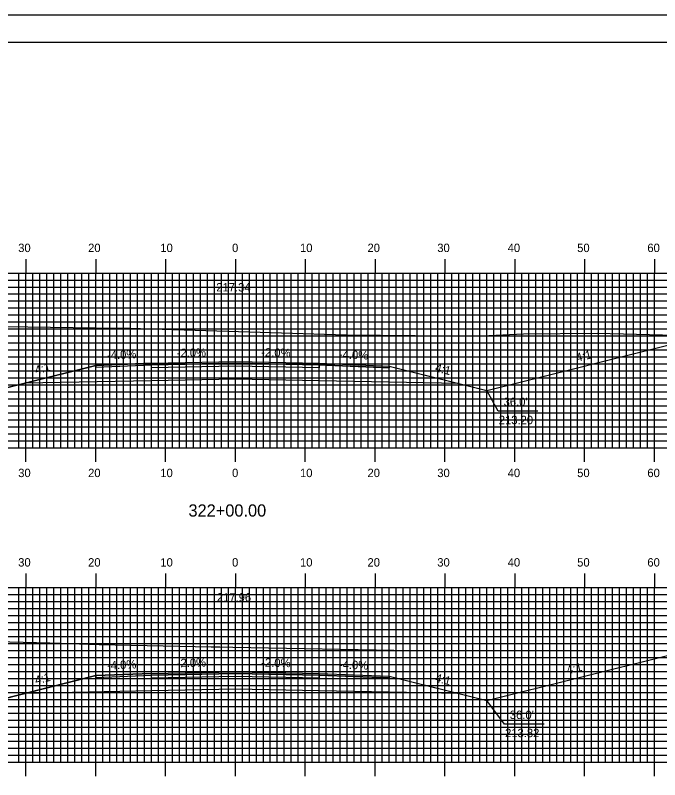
# Model space of a CAD drawing. Extents: x 1820424 to 1820768, y 442591 to 442811.
# Drawn here: x 1820558.7 to 1820650.9, y 442701.2 to 442810.5 of the extents above; entities that cross this region are included whole.
import ezdxf

# ---------------------------------------------------------------- set-up
doc = ezdxf.new("R2010")
doc.units = 0
for name, color, linetype in [('ANNOTATION', 7, 'Continuous'), ('BORDER', 7, 'Continuous'), ('D_Roadway_Centerline', 7, 'Continuous'), ('D_Roadway_Centerline_Text', 7, 'Continuous'), ('D_Roadway_Edge_Shoulder', 7, 'Continuous'), ('D_Roadway_Edge_TW', 7, 'Continuous'), ('D_Roadway_Pavement', 7, 'Continuous'), ('D_Roadway_SlopeLines', 7, 'Continuous'), ('D_Roadway_SubGrade', 7, 'Continuous'), ('H_V ANNOTATION', 7, 'Continuous'), ('MAJOR', 7, 'Continuous'), ('MINOR', 7, 'Continuous'), ('PLOT BOUNDARY', 7, 'Continuous'), ('S_Roadway_Centerline', 7, 'Continuous')]:
    doc.layers.add(name, color=color, linetype=linetype)

msp = doc.modelspace()

# ---------------------------------------------------------------- linework, layer by layer
at = {"layer": 'ANNOTATION'}
for points in [[(1820633.52, 442753.92), (1820627.82, 442753.92), (1820626.2, 442756.86)], [(1820634.41, 442709.14), (1820628.72, 442709.14), (1820626.2, 442712.49)]]:
    msp.add_lwpolyline(points, dxfattribs=at)
at = {"layer": 'BORDER'}
msp.add_lwpolyline([(1820440.6, 442596.67), (1820760.6, 442596.67), (1820760.6, 442806.67), (1820440.6, 442806.67)], close=True, dxfattribs=at)
at = {"layer": 'D_Roadway_Centerline'}
for points in [[(1820513.87, 442766.87), (1820515.12, 442766.81), (1820516.37, 442766.67), (1820517.62, 442766.46), (1820518.87, 442766.19), (1820556.03, 442756.9), (1820560.03, 442757.9), (1820570.2, 442760.44), (1820578.2, 442760.76), (1820590.2, 442761), (1820602.2, 442760.76), (1820612.2, 442760.36), (1820622.2, 442757.86), (1820626.2, 442756.86), (1820654.98, 442764.06), (1820656.23, 442764.33), (1820657.48, 442764.52), (1820658.73, 442764.63), (1820659.98, 442764.66)], [(1820513.66, 442722.46), (1820514.91, 442722.44), (1820516.16, 442722.33), (1820517.41, 442722.14), (1820518.66, 442721.87), (1820556.03, 442712.52), (1820560.03, 442713.52), (1820570.2, 442716.07), (1820578.2, 442716.39), (1820590.2, 442716.63), (1820602.2, 442716.39), (1820612.2, 442715.99), (1820622.2, 442713.49), (1820626.2, 442712.49), (1820652.27, 442719), (1820653.52, 442719.27), (1820654.77, 442719.47), (1820656.02, 442719.58), (1820657.27, 442719.62)]]:
    msp.add_lwpolyline(points, dxfattribs=at)
at = {"layer": 'D_Roadway_Edge_Shoulder'}
for points in [[(1820578.2, 442760.76), (1820570.2, 442760.44), (1820570.2, 442760.19), (1820578.2, 442760.51)], [(1820602.2, 442760.76), (1820612.2, 442760.36), (1820612.2, 442760.11), (1820602.2, 442760.51)], [(1820578.2, 442716.39), (1820570.2, 442716.07), (1820570.2, 442715.82), (1820578.2, 442716.14)], [(1820602.2, 442716.39), (1820612.2, 442715.99), (1820612.2, 442715.74), (1820602.2, 442716.14)]]:
    msp.add_lwpolyline(points, close=True, dxfattribs=at)
at = {"layer": 'D_Roadway_Edge_TW'}
for points in [[(1820578.2, 442760.51), (1820578.2, 442760.76), (1820590.2, 442761), (1820602.2, 442760.76), (1820602.2, 442760.51), (1820590.2, 442760.75)], [(1820578.2, 442716.14), (1820578.2, 442716.39), (1820590.2, 442716.63), (1820602.2, 442716.39), (1820602.2, 442716.14), (1820590.2, 442716.38)]]:
    msp.add_lwpolyline(points, close=True, dxfattribs=at)
at = {"layer": 'D_Roadway_Pavement'}
for points in [[(1820578.2, 442760.09), (1820578.2, 442760.51), (1820590.2, 442760.75), (1820602.2, 442760.51), (1820602.2, 442760.09), (1820590.2, 442760.33)], [(1820578.2, 442715.72), (1820578.2, 442716.14), (1820590.2, 442716.38), (1820602.2, 442716.14), (1820602.2, 442715.72), (1820590.2, 442715.96)]]:
    msp.add_lwpolyline(points, close=True, dxfattribs=at)
at = {"layer": 'D_Roadway_SlopeLines'}
for points in [[(1820626.2, 442756.86), (1820654.98, 442764.06), (1820656.23, 442764.33), (1820657.48, 442764.52), (1820658.73, 442764.63), (1820659.98, 442764.66)], [(1820570.2, 442760.44), (1820556.03, 442756.9)], [(1820612.2, 442760.36), (1820626.2, 442756.86)], [(1820626.2, 442712.49), (1820652.27, 442719), (1820653.52, 442719.27), (1820654.77, 442719.47), (1820656.02, 442719.58), (1820657.27, 442719.62)], [(1820570.2, 442716.07), (1820556.03, 442712.52)], [(1820612.2, 442715.99), (1820626.2, 442712.49)]]:
    msp.add_lwpolyline(points, dxfattribs=at)
at = {"layer": 'D_Roadway_SubGrade'}
for points in [[(1820578.2, 442758.26), (1820560.03, 442757.9), (1820570.2, 442760.44), (1820570.2, 442760.19), (1820578.2, 442760.51), (1820590.2, 442760.75), (1820602.2, 442760.51), (1820612.2, 442760.11), (1820612.2, 442760.36), (1820622.2, 442757.86), (1820602.2, 442758.26), (1820590.2, 442758.5)], [(1820578.2, 442713.89), (1820560.03, 442713.52), (1820570.2, 442716.07), (1820570.2, 442715.82), (1820578.2, 442716.14), (1820590.2, 442716.38), (1820602.2, 442716.14), (1820612.2, 442715.74), (1820612.2, 442715.99), (1820622.2, 442713.49), (1820602.2, 442713.89), (1820590.2, 442714.13)]]:
    msp.add_lwpolyline(points, close=True, dxfattribs=at)
at = {"layer": 'MAJOR'}
for p, q in [((1820560.2, 442775.67), (1820560.2, 442773.67)), ((1820570.2, 442775.67), (1820570.2, 442773.67)), ((1820580.2, 442775.67), (1820580.2, 442773.67)), ((1820590.2, 442775.67), (1820590.2, 442773.67)), ((1820600.2, 442775.67), (1820600.2, 442773.67)), ((1820610.2, 442775.67), (1820610.2, 442773.67)), ((1820620.2, 442775.67), (1820620.2, 442773.67)), ((1820630.2, 442775.67), (1820630.2, 442773.67)), ((1820640.2, 442775.67), (1820640.2, 442773.67)), ((1820650.2, 442775.67), (1820650.2, 442773.67)), ((1820450.2, 442773.67), (1820730.2, 442773.67)), ((1820450.2, 442773.67), (1820730.2, 442773.67)), ((1820560.2, 442748.67), (1820560.2, 442773.67)), ((1820570.2, 442748.67), (1820570.2, 442773.67)), ((1820580.2, 442748.67), (1820580.2, 442773.67)), ((1820590.2, 442748.67), (1820590.2, 442773.67)), ((1820600.2, 442748.67), (1820600.2, 442773.67)), ((1820610.2, 442748.67), (1820610.2, 442773.67)), ((1820620.2, 442748.67), (1820620.2, 442773.67)), ((1820630.2, 442748.67), (1820630.2, 442773.67)), ((1820640.2, 442748.67), (1820640.2, 442773.67)), ((1820650.2, 442748.67), (1820650.2, 442773.67)), ((1820450.2, 442768.67), (1820730.2, 442768.67)), ((1820450.2, 442763.67), (1820730.2, 442763.67)), ((1820450.2, 442758.67), (1820730.2, 442758.67)), ((1820450.2, 442753.67), (1820730.2, 442753.67)), ((1820450.2, 442748.67), (1820730.2, 442748.67)), ((1820450.2, 442748.67), (1820730.2, 442748.67)), ((1820560.2, 442746.66), (1820560.2, 442748.67)), ((1820570.2, 442746.66), (1820570.2, 442748.67)), ((1820580.2, 442746.66), (1820580.2, 442748.67)), ((1820590.2, 442746.66), (1820590.2, 442748.67)), ((1820600.2, 442746.66), (1820600.2, 442748.67)), ((1820610.2, 442746.66), (1820610.2, 442748.67)), ((1820620.2, 442746.66), (1820620.2, 442748.67)), ((1820630.2, 442746.66), (1820630.2, 442748.67)), ((1820640.2, 442746.66), (1820640.2, 442748.67)), ((1820650.2, 442746.66), (1820650.2, 442748.67)), ((1820560.2, 442730.67), (1820560.2, 442728.67)), ((1820570.2, 442730.67), (1820570.2, 442728.67)), ((1820580.2, 442730.67), (1820580.2, 442728.67)), ((1820590.2, 442730.67), (1820590.2, 442728.67)), ((1820600.2, 442730.67), (1820600.2, 442728.67)), ((1820610.2, 442730.67), (1820610.2, 442728.67)), ((1820620.2, 442730.67), (1820620.2, 442728.67)), ((1820630.2, 442730.67), (1820630.2, 442728.67)), ((1820640.2, 442730.67), (1820640.2, 442728.67)), ((1820650.2, 442730.67), (1820650.2, 442728.67)), ((1820450.2, 442728.67), (1820730.2, 442728.67)), ((1820450.2, 442728.67), (1820730.2, 442728.67)), ((1820560.2, 442703.67), (1820560.2, 442728.67)), ((1820570.2, 442703.67), (1820570.2, 442728.67)), ((1820580.2, 442703.67), (1820580.2, 442728.67)), ((1820590.2, 442703.67), (1820590.2, 442728.67)), ((1820600.2, 442703.67), (1820600.2, 442728.67)), ((1820610.2, 442703.67), (1820610.2, 442728.67)), ((1820620.2, 442703.67), (1820620.2, 442728.67)), ((1820630.2, 442703.67), (1820630.2, 442728.67)), ((1820640.2, 442703.67), (1820640.2, 442728.67)), ((1820650.2, 442703.67), (1820650.2, 442728.67)), ((1820450.2, 442723.67), (1820730.2, 442723.67)), ((1820450.2, 442718.67), (1820730.2, 442718.67)), ((1820450.2, 442713.67), (1820730.2, 442713.67)), ((1820450.2, 442708.67), (1820730.2, 442708.67)), ((1820450.2, 442703.67), (1820730.2, 442703.67)), ((1820450.2, 442703.67), (1820730.2, 442703.67)), ((1820560.2, 442701.66), (1820560.2, 442703.67)), ((1820570.2, 442701.66), (1820570.2, 442703.67)), ((1820580.2, 442701.66), (1820580.2, 442703.67)), ((1820590.2, 442701.66), (1820590.2, 442703.67)), ((1820600.2, 442701.66), (1820600.2, 442703.67)), ((1820610.2, 442701.66), (1820610.2, 442703.67)), ((1820620.2, 442701.66), (1820620.2, 442703.67)), ((1820630.2, 442701.66), (1820630.2, 442703.67)), ((1820640.2, 442701.66), (1820640.2, 442703.67)), ((1820650.2, 442701.66), (1820650.2, 442703.67))]:
    msp.add_line(p, q, dxfattribs=at)
at = {"layer": 'MINOR'}
for p, q in [((1820559.2, 442748.67), (1820559.2, 442773.67)), ((1820561.2, 442748.67), (1820561.2, 442773.67)), ((1820562.2, 442748.67), (1820562.2, 442773.67)), ((1820563.2, 442748.67), (1820563.2, 442773.67)), ((1820564.2, 442748.67), (1820564.2, 442773.67)), ((1820565.2, 442748.67), (1820565.2, 442773.67)), ((1820566.2, 442748.67), (1820566.2, 442773.67)), ((1820567.2, 442748.67), (1820567.2, 442773.67)), ((1820568.2, 442748.67), (1820568.2, 442773.67)), ((1820569.2, 442748.67), (1820569.2, 442773.67)), ((1820571.2, 442748.67), (1820571.2, 442773.67)), ((1820572.2, 442748.67), (1820572.2, 442773.67)), ((1820573.2, 442748.67), (1820573.2, 442773.67)), ((1820574.2, 442748.67), (1820574.2, 442773.67)), ((1820575.2, 442748.67), (1820575.2, 442773.67)), ((1820576.2, 442748.67), (1820576.2, 442773.67)), ((1820577.2, 442748.67), (1820577.2, 442773.67)), ((1820578.2, 442748.67), (1820578.2, 442773.67)), ((1820579.2, 442748.67), (1820579.2, 442773.67)), ((1820581.2, 442748.67), (1820581.2, 442773.67)), ((1820582.2, 442748.67), (1820582.2, 442773.67)), ((1820583.2, 442748.67), (1820583.2, 442773.67)), ((1820584.2, 442748.67), (1820584.2, 442773.67)), ((1820585.2, 442748.67), (1820585.2, 442773.67)), ((1820586.2, 442748.67), (1820586.2, 442773.67)), ((1820587.2, 442748.67), (1820587.2, 442773.67)), ((1820588.2, 442748.67), (1820588.2, 442773.67)), ((1820589.2, 442748.67), (1820589.2, 442773.67)), ((1820591.2, 442748.67), (1820591.2, 442773.67)), ((1820592.2, 442748.67), (1820592.2, 442773.67)), ((1820593.2, 442748.67), (1820593.2, 442773.67)), ((1820594.2, 442748.67), (1820594.2, 442773.67)), ((1820595.2, 442748.67), (1820595.2, 442773.67)), ((1820596.2, 442748.67), (1820596.2, 442773.67)), ((1820597.2, 442748.67), (1820597.2, 442773.67)), ((1820598.2, 442748.67), (1820598.2, 442773.67)), ((1820599.2, 442748.67), (1820599.2, 442773.67)), ((1820601.2, 442748.67), (1820601.2, 442773.67)), ((1820602.2, 442748.67), (1820602.2, 442773.67)), ((1820603.2, 442748.67), (1820603.2, 442773.67)), ((1820604.2, 442748.67), (1820604.2, 442773.67)), ((1820605.2, 442748.67), (1820605.2, 442773.67)), ((1820606.2, 442748.67), (1820606.2, 442773.67)), ((1820607.2, 442748.67), (1820607.2, 442773.67)), ((1820608.2, 442748.67), (1820608.2, 442773.67)), ((1820609.2, 442748.67), (1820609.2, 442773.67)), ((1820611.2, 442748.67), (1820611.2, 442773.67)), ((1820612.2, 442748.67), (1820612.2, 442773.67)), ((1820613.2, 442748.67), (1820613.2, 442773.67)), ((1820614.2, 442748.67), (1820614.2, 442773.67)), ((1820615.2, 442748.67), (1820615.2, 442773.67)), ((1820616.2, 442748.67), (1820616.2, 442773.67)), ((1820617.2, 442748.67), (1820617.2, 442773.67)), ((1820618.2, 442748.67), (1820618.2, 442773.67)), ((1820619.2, 442748.67), (1820619.2, 442773.67)), ((1820621.2, 442748.67), (1820621.2, 442773.67)), ((1820622.2, 442748.67), (1820622.2, 442773.67)), ((1820623.2, 442748.67), (1820623.2, 442773.67)), ((1820624.2, 442748.67), (1820624.2, 442773.67)), ((1820625.2, 442748.67), (1820625.2, 442773.67)), ((1820626.2, 442748.67), (1820626.2, 442773.67)), ((1820627.2, 442748.67), (1820627.2, 442773.67)), ((1820628.2, 442748.67), (1820628.2, 442773.67)), ((1820629.2, 442748.67), (1820629.2, 442773.67)), ((1820631.2, 442748.67), (1820631.2, 442773.67)), ((1820632.2, 442748.67), (1820632.2, 442773.67)), ((1820633.2, 442748.67), (1820633.2, 442773.67)), ((1820634.2, 442748.67), (1820634.2, 442773.67)), ((1820635.2, 442748.67), (1820635.2, 442773.67)), ((1820636.2, 442748.67), (1820636.2, 442773.67)), ((1820637.2, 442748.67), (1820637.2, 442773.67)), ((1820638.2, 442748.67), (1820638.2, 442773.67)), ((1820639.2, 442748.67), (1820639.2, 442773.67)), ((1820641.2, 442748.67), (1820641.2, 442773.67)), ((1820642.2, 442748.67), (1820642.2, 442773.67)), ((1820643.2, 442748.67), (1820643.2, 442773.67)), ((1820644.2, 442748.67), (1820644.2, 442773.67)), ((1820645.2, 442748.67), (1820645.2, 442773.67)), ((1820646.2, 442748.67), (1820646.2, 442773.67)), ((1820647.2, 442748.67), (1820647.2, 442773.67)), ((1820648.2, 442748.67), (1820648.2, 442773.67)), ((1820649.2, 442748.67), (1820649.2, 442773.67)), ((1820450.2, 442772.67), (1820730.2, 442772.67)), ((1820450.2, 442771.67), (1820730.2, 442771.67)), ((1820450.2, 442770.67), (1820730.2, 442770.67)), ((1820450.2, 442769.67), (1820730.2, 442769.67)), ((1820450.2, 442767.67), (1820730.2, 442767.67)), ((1820450.2, 442766.67), (1820730.2, 442766.67)), ((1820450.2, 442765.67), (1820730.2, 442765.67)), ((1820450.2, 442764.67), (1820730.2, 442764.67)), ((1820450.2, 442762.67), (1820730.2, 442762.67)), ((1820450.2, 442761.67), (1820730.2, 442761.67)), ((1820450.2, 442760.67), (1820730.2, 442760.67)), ((1820450.2, 442759.67), (1820730.2, 442759.67)), ((1820450.2, 442757.67), (1820730.2, 442757.67)), ((1820450.2, 442756.67), (1820730.2, 442756.67)), ((1820450.2, 442755.67), (1820730.2, 442755.67)), ((1820450.2, 442754.67), (1820730.2, 442754.67)), ((1820450.2, 442752.67), (1820730.2, 442752.67)), ((1820450.2, 442751.67), (1820730.2, 442751.67)), ((1820450.2, 442750.67), (1820730.2, 442750.67)), ((1820450.2, 442749.67), (1820730.2, 442749.67)), ((1820559.2, 442703.67), (1820559.2, 442728.67)), ((1820561.2, 442703.67), (1820561.2, 442728.67)), ((1820562.2, 442703.67), (1820562.2, 442728.67)), ((1820563.2, 442703.67), (1820563.2, 442728.67)), ((1820564.2, 442703.67), (1820564.2, 442728.67)), ((1820565.2, 442703.67), (1820565.2, 442728.67)), ((1820566.2, 442703.67), (1820566.2, 442728.67)), ((1820567.2, 442703.67), (1820567.2, 442728.67)), ((1820568.2, 442703.67), (1820568.2, 442728.67)), ((1820569.2, 442703.67), (1820569.2, 442728.67)), ((1820571.2, 442703.67), (1820571.2, 442728.67)), ((1820572.2, 442703.67), (1820572.2, 442728.67)), ((1820573.2, 442703.67), (1820573.2, 442728.67)), ((1820574.2, 442703.67), (1820574.2, 442728.67)), ((1820575.2, 442703.67), (1820575.2, 442728.67)), ((1820576.2, 442703.67), (1820576.2, 442728.67)), ((1820577.2, 442703.67), (1820577.2, 442728.67)), ((1820578.2, 442703.67), (1820578.2, 442728.67)), ((1820579.2, 442703.67), (1820579.2, 442728.67)), ((1820581.2, 442703.67), (1820581.2, 442728.67)), ((1820582.2, 442703.67), (1820582.2, 442728.67)), ((1820583.2, 442703.67), (1820583.2, 442728.67)), ((1820584.2, 442703.67), (1820584.2, 442728.67)), ((1820585.2, 442703.67), (1820585.2, 442728.67)), ((1820586.2, 442703.67), (1820586.2, 442728.67)), ((1820587.2, 442703.67), (1820587.2, 442728.67)), ((1820588.2, 442703.67), (1820588.2, 442728.67)), ((1820589.2, 442703.67), (1820589.2, 442728.67)), ((1820591.2, 442703.67), (1820591.2, 442728.67)), ((1820592.2, 442703.67), (1820592.2, 442728.67)), ((1820593.2, 442703.67), (1820593.2, 442728.67)), ((1820594.2, 442703.67), (1820594.2, 442728.67)), ((1820595.2, 442703.67), (1820595.2, 442728.67)), ((1820596.2, 442703.67), (1820596.2, 442728.67)), ((1820597.2, 442703.67), (1820597.2, 442728.67)), ((1820598.2, 442703.67), (1820598.2, 442728.67)), ((1820599.2, 442703.67), (1820599.2, 442728.67)), ((1820601.2, 442703.67), (1820601.2, 442728.67)), ((1820602.2, 442703.67), (1820602.2, 442728.67)), ((1820603.2, 442703.67), (1820603.2, 442728.67)), ((1820604.2, 442703.67), (1820604.2, 442728.67)), ((1820605.2, 442703.67), (1820605.2, 442728.67)), ((1820606.2, 442703.67), (1820606.2, 442728.67)), ((1820607.2, 442703.67), (1820607.2, 442728.67)), ((1820608.2, 442703.67), (1820608.2, 442728.67)), ((1820609.2, 442703.67), (1820609.2, 442728.67)), ((1820611.2, 442703.67), (1820611.2, 442728.67)), ((1820612.2, 442703.67), (1820612.2, 442728.67)), ((1820613.2, 442703.67), (1820613.2, 442728.67)), ((1820614.2, 442703.67), (1820614.2, 442728.67)), ((1820615.2, 442703.67), (1820615.2, 442728.67)), ((1820616.2, 442703.67), (1820616.2, 442728.67)), ((1820617.2, 442703.67), (1820617.2, 442728.67)), ((1820618.2, 442703.67), (1820618.2, 442728.67)), ((1820619.2, 442703.67), (1820619.2, 442728.67)), ((1820621.2, 442703.67), (1820621.2, 442728.67)), ((1820622.2, 442703.67), (1820622.2, 442728.67)), ((1820623.2, 442703.67), (1820623.2, 442728.67)), ((1820624.2, 442703.67), (1820624.2, 442728.67)), ((1820625.2, 442703.67), (1820625.2, 442728.67)), ((1820626.2, 442703.67), (1820626.2, 442728.67)), ((1820627.2, 442703.67), (1820627.2, 442728.67)), ((1820628.2, 442703.67), (1820628.2, 442728.67)), ((1820629.2, 442703.67), (1820629.2, 442728.67)), ((1820631.2, 442703.67), (1820631.2, 442728.67)), ((1820632.2, 442703.67), (1820632.2, 442728.67)), ((1820633.2, 442703.67), (1820633.2, 442728.67)), ((1820634.2, 442703.67), (1820634.2, 442728.67)), ((1820635.2, 442703.67), (1820635.2, 442728.67)), ((1820636.2, 442703.67), (1820636.2, 442728.67)), ((1820637.2, 442703.67), (1820637.2, 442728.67)), ((1820638.2, 442703.67), (1820638.2, 442728.67)), ((1820639.2, 442703.67), (1820639.2, 442728.67)), ((1820641.2, 442703.67), (1820641.2, 442728.67)), ((1820642.2, 442703.67), (1820642.2, 442728.67)), ((1820643.2, 442703.67), (1820643.2, 442728.67)), ((1820644.2, 442703.67), (1820644.2, 442728.67)), ((1820645.2, 442703.67), (1820645.2, 442728.67)), ((1820646.2, 442703.67), (1820646.2, 442728.67)), ((1820647.2, 442703.67), (1820647.2, 442728.67)), ((1820648.2, 442703.67), (1820648.2, 442728.67)), ((1820649.2, 442703.67), (1820649.2, 442728.67)), ((1820450.2, 442727.67), (1820730.2, 442727.67)), ((1820450.2, 442726.67), (1820730.2, 442726.67)), ((1820450.2, 442725.67), (1820730.2, 442725.67)), ((1820450.2, 442724.67), (1820730.2, 442724.67)), ((1820450.2, 442722.67), (1820730.2, 442722.67)), ((1820450.2, 442721.67), (1820730.2, 442721.67)), ((1820450.2, 442720.67), (1820730.2, 442720.67)), ((1820450.2, 442719.67), (1820730.2, 442719.67)), ((1820450.2, 442717.67), (1820730.2, 442717.67)), ((1820450.2, 442716.67), (1820730.2, 442716.67)), ((1820450.2, 442715.67), (1820730.2, 442715.67)), ((1820450.2, 442714.67), (1820730.2, 442714.67)), ((1820450.2, 442712.67), (1820730.2, 442712.67)), ((1820450.2, 442711.67), (1820730.2, 442711.67)), ((1820450.2, 442710.67), (1820730.2, 442710.67)), ((1820450.2, 442709.67), (1820730.2, 442709.67)), ((1820450.2, 442707.67), (1820730.2, 442707.67)), ((1820450.2, 442706.67), (1820730.2, 442706.67)), ((1820450.2, 442705.67), (1820730.2, 442705.67)), ((1820450.2, 442704.67), (1820730.2, 442704.67))]:
    msp.add_line(p, q, dxfattribs=at)
at = {"layer": 'PLOT BOUNDARY'}
msp.add_lwpolyline([(1820424.42, 442590.55), (1820764.42, 442590.55), (1820764.42, 442810.55), (1820424.42, 442810.55)], close=True, dxfattribs=at)
at = {"layer": 'S_Roadway_Centerline'}
for points in [[(1820450.2, 442767.88), (1820454.43, 442767.81), (1820456.57, 442767.78), (1820461.62, 442767.61), (1820472.98, 442767.23), (1820483.25, 442767.34), (1820489.5, 442767.31), (1820500.41, 442767.14), (1820506.6, 442767.04), (1820524.28, 442766.63), (1820540.55, 442766.4), (1820550.14, 442766.1), (1820557.24, 442766.04), (1820570.2, 442765.82), (1820575.02, 442765.8), (1820589.12, 442765.34), (1820606.04, 442764.82), (1820615.95, 442764.71), (1820625.49, 442764.7), (1820631.43, 442764.99), (1820642, 442765.07), (1820655.12, 442764.74)], [(1820502.48, 442722.35), (1820520.29, 442722.53), (1820520.93, 442722.55), (1820521.25, 442722.54), (1820523.25, 442722.38), (1820535.25, 442721.39), (1820537.21, 442721.26), (1820548.29, 442721.07), (1820554.03, 442721), (1820563.61, 442720.77), (1820570.69, 442720.52), (1820586.74, 442720.2), (1820587.5, 442720.18), (1820587.95, 442720.18), (1820589.81, 442720.13), (1820615.47, 442719.64), (1820621.46, 442719.6), (1820627.75, 442719.67), (1820654.9, 442719.63)]]:
    msp.add_lwpolyline(points, dxfattribs=at)

# ---------------------------------------------------------------- texts
at = {"layer": 'ANNOTATION'}
for s, rotation, p in [('-4.0%', 2.2906, (1820571.84, 442761.31)), ('-2.0%', 1.1458, (1820581.81, 442761.63)), ('-2.0%', 358.8542, (1820593.89, 442761.73)), ('-4.0%', 357.7094, (1820605, 442761.45)), ('4:1', 14.0362, (1820639.13, 442760.95)), ('4:1', 14.0362, (1820561.65, 442759.17)), ('4:1', 345.9638, (1820618.71, 442759.6)), ('-2.0%', 1.1458, (1820581.81, 442717.26)), ('-2.0%', 358.8542, (1820593.89, 442717.35)), ('-4.0%', 2.2906, (1820571.84, 442716.93)), ('-4.0%', 357.7094, (1820605, 442717.08)), ('4:1', 14.0362, (1820637.77, 442716.24)), ('4:1', 14.0362, (1820561.65, 442714.79)), ('4:1', 345.9638, (1820618.71, 442715.22))]:
    msp.add_text(s, height=1.2, rotation=rotation, dxfattribs=at).set_placement(p)
for s, p in [("36.0'", (1820628.6, 442754.64)), ('213.20', (1820627.91, 442752.04)), ("36.0'", (1820629.49, 442709.86)), ('213.82', (1820628.81, 442707.26))]:
    msp.add_text(s, height=1.2, dxfattribs=at).set_placement(p)
at = {"layer": 'D_Roadway_Centerline'}
for s, p in [('C', (1820590.2, 442761)), ('L', (1820590.2, 442760.99)), ('C', (1820590.2, 442716.63)), ('L', (1820590.2, 442716.62))]:
    msp.add_text(s, height=0.0146, dxfattribs=at).set_placement(p)
at = {"layer": 'D_Roadway_Centerline_Text'}
for s, p in [('217.34', (1820587.46, 442771.03)), ('217.96', (1820587.54, 442726.66))]:
    msp.add_text(s, height=1.2, dxfattribs=at).set_placement(p)
at = {"layer": 'H_V ANNOTATION'}
for s, height, p in [('30', 1.2, (1820559.1, 442776.67)), ('20', 1.2, (1820569.11, 442776.67)), ('10', 1.2, (1820579.45, 442776.67)), ('0', 1.2, (1820589.72, 442776.67)), ('10', 1.2, (1820599.45, 442776.67)), ('20', 1.2, (1820609.11, 442776.67)), ('30', 1.2, (1820619.1, 442776.67)), ('40', 1.2, (1820629.18, 442776.67)), ('50', 1.2, (1820639.13, 442776.67)), ('60', 1.2, (1820649.18, 442776.67)), ('30', 1.2, (1820559.1, 442744.47)), ('20', 1.2, (1820569.11, 442744.47)), ('10', 1.2, (1820579.45, 442744.47)), ('0', 1.2, (1820589.72, 442744.47)), ('10', 1.2, (1820599.45, 442744.47)), ('20', 1.2, (1820609.11, 442744.47)), ('30', 1.2, (1820619.1, 442744.47)), ('40', 1.2, (1820629.18, 442744.47)), ('50', 1.2, (1820639.13, 442744.47)), ('60', 1.2, (1820649.18, 442744.47)), ('322+00.00', 1.75, (1820583.48, 442738.82)), ('30', 1.2, (1820559.1, 442731.67)), ('20', 1.2, (1820569.11, 442731.67)), ('10', 1.2, (1820579.45, 442731.67)), ('0', 1.2, (1820589.72, 442731.67)), ('10', 1.2, (1820599.45, 442731.67)), ('20', 1.2, (1820609.11, 442731.67)), ('30', 1.2, (1820619.1, 442731.67)), ('40', 1.2, (1820629.18, 442731.67)), ('50', 1.2, (1820639.13, 442731.67)), ('60', 1.2, (1820649.18, 442731.67))]:
    msp.add_text(s, height=height, dxfattribs=at).set_placement(p)

doc.saveas('drawing.dxf')
